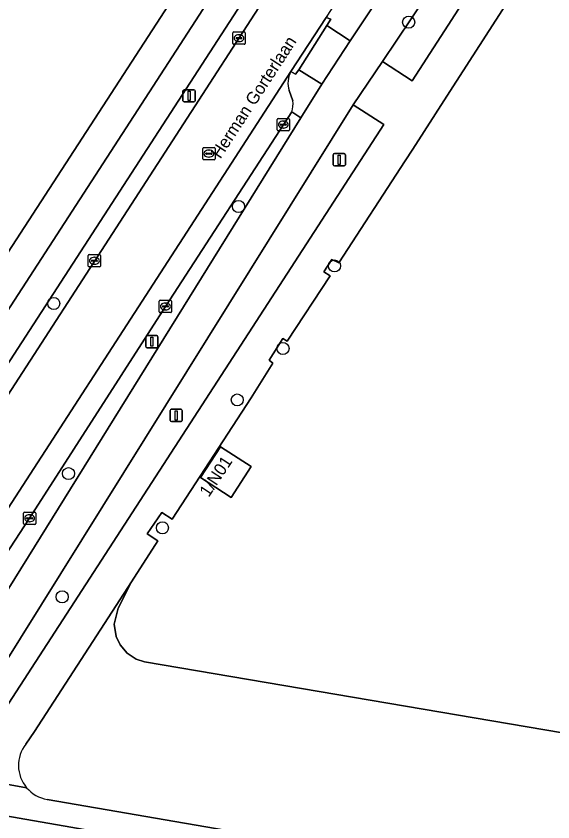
# Model space of a CAD drawing. Extents: x 161258 to 161838, y 380833 to 381727.
# Drawn here: x 161521.6 to 161565.2, y 380871.5 to 380937 of the extents above; entities that cross this region are included whole.
import ezdxf

# ---------------------------------------------------------------- set-up
doc = ezdxf.new("R2010")
doc.units = 0
for name, color, linetype in [('IMGEO_Berm_groen', 7, 'Continuous'), ('IMGEO_Berm_halfverhard', 7, 'Continuous'), ('IMGEO_Berm_open', 7, 'Continuous'), ('IMGEO_Boom', 7, 'Continuous'), ('IMGEO_Erf', 7, 'Continuous'), ('IMGEO_Fietspad_gesloten', 7, 'Continuous'), ('IMGEO_Kolk', 7, 'Continuous'), ('IMGEO_Lichtmast', 7, 'Continuous'), ('IMGEO_Loofbos', 7, 'Continuous'), ('IMGEO_Openbare_ruimte_label', 7, 'Continuous'), ('IMGEO_Pand', 7, 'Continuous'), ('IMGEO_Pand_nummerreeks', 7, 'Continuous'), ('IMGEO_Parkeervlak_open', 7, 'Continuous'), ('IMGEO_Rijbaan_lokaal_open', 7, 'Continuous'), ('IMGEO_Rioolput', 7, 'Continuous'), ('IMGEO_Voetpad_gesloten', 7, 'Continuous'), ('IMGEO_Voetpad_open', 7, 'Continuous')]:
    doc.layers.add(name, color=color, linetype=linetype)

msp = doc.modelspace()

# ---------------------------------------------------------------- linework, layer by layer
at = {"layer": 'IMGEO_Berm_groen'}
msp.add_lwpolyline([(161575.815, 380965.914), (161576.339, 380966.695), (161577.485, 380968.471), (161575.243, 380968.987), (161573.978, 380967.07), (161573.428, 380966.238), (161551.302, 380933.307), (161553.723, 380931.738)], close=True, dxfattribs=at)
for points in [[(161546.812, 380936.989), (161546.739, 380936.876), (161547.104, 380936.735), (161546.794, 380936.22), (161548.686, 380934.993), (161550.756, 380938.063)], [(161546.385, 380931.453), (161544.513, 380932.638), (161544.243, 380932.26), (161543.871, 380932.477)], [(161543.742, 380930.939), (161544.035, 380930.109)], [(161543.938, 380929.207), (161544.685, 380928.722), (161546.385, 380931.453)], [(161551.434, 380928.192), (161548.922, 380929.776), (161516.774, 380878.276), (161515.901, 380876.852)], [(161515.875, 380875.503), (161517.075, 380875.292), (161519.332, 380878.728), (161551.434, 380928.192)]]:
    msp.add_lwpolyline(points, dxfattribs=at)
for centre, radius, start, end in [((161545.488, 380931.567), 1.856, 150.63017, 199.78089), ((161542.148, 380929.856), 1.904, 340.07765, 7.64649)]:
    msp.add_arc(centre, radius, start, end, dxfattribs=at)
at = {"layer": 'IMGEO_Berm_halfverhard'}
msp.add_lwpolyline([(161544.685, 380928.722), (161543.938, 380929.207), (161533.683, 380913.408), (161522.653, 380896.207), (161515.229, 380884.867), (161513.994, 380883.019), (161515.665, 380882.025), (161515.927, 380882.459)], close=True, dxfattribs=at)
at = {"layer": 'IMGEO_Berm_open'}
msp.add_lwpolyline([(161544.901, 380943.304), (161544.547, 380943.54), (161551.119, 380953.696), (161550.334, 380954.192), (161506.413, 380886.439), (161503.381, 380881.765), (161504.523, 380881.003), (161505.64, 380882.718)], close=True, dxfattribs=at)
at = {"layer": 'IMGEO_Boom'}
for centre in [(161553.439, 380936.496), (161539.621, 380921.529), (161547.413, 380916.696), (161524.614, 380913.646), (161543.23, 380909.996), (161539.52, 380905.815), (161525.812, 380899.834), (161533.438, 380895.426), (161525.296, 380889.829)]:
    msp.add_circle(centre, 0.489, dxfattribs=at)
at = {"layer": 'IMGEO_Erf'}
for points in [[(161490.257, 380892.689), (161494.395, 380889.926), (161494.323, 380889.817), (161500.227, 380885.918), (161501.31, 380887.571), (161502.49, 380889.425), (161513.725, 380906.807), (161512.888, 380907.32), (161515.02, 380910.631), (161515.878, 380910.106), (161540.302, 380947.69), (161546.174, 380956.722), (161554.834, 380970.332), (161556.123, 380972.241), (161556.737, 380973.185), (161558.236, 380975.49), (161576.218, 381003.146)], [(161579.588, 380966.248), (161556.537, 380930.473), (161553.779, 380926.192), (161553.165, 380925.238), (161547.753, 380916.964), (161547.209, 380917.209), (161546.55, 380916.226), (161547.061, 380915.899), (161543.578, 380910.592), (161543.218, 380910.801), (161542.1, 380909.047), (161542.416, 380908.796), (161540.643, 380905.976), (161534.24, 380896.125), (161533.387, 380896.677), (161532.197, 380894.942), (161533.069, 380894.385), (161530.918, 380891.057), (161529.831, 380888.91), (161529.531, 380887.614), (161529.683, 380886.616), (161530.003, 380885.931), (161530.573, 380885.257), (161531.3, 380884.776), (161531.988, 380884.543), (161635.09, 380867.033)]]:
    msp.add_lwpolyline(points, dxfattribs=at)
msp.add_lwpolyline([(161539.026, 380897.897), (161536.533, 380899.52), (161538.15, 380902.004), (161540.639, 380900.399)], close=True, dxfattribs=at)
at = {"layer": 'IMGEO_Fietspad_gesloten'}
for points in [[(161595.079, 381027.823), (161594.29, 381026.415), (161590.696, 381020.856), (161581.633, 381006.84), (161581.562, 381006.731), (161578.938, 381002.688), (161504.207, 380887.394), (161498.991, 380879.345)], [(161608.896, 381024.645), (161604.863, 381018.421), (161604.793, 381018.314), (161595.419, 381004.467), (161595.345, 381004.358), (161592.619, 381000.32), (161590.6, 380997.205), (161582.149, 380984.599), (161579.947, 380981.315), (161576.319, 380975.904), (161571.939, 380969.459), (161570.664, 380967.582), (161565.851, 380960.445), (161550.756, 380938.063), (161548.686, 380934.993), (161546.385, 380931.453), (161544.685, 380928.722), (161515.927, 380882.459), (161515.665, 380882.025), (161513.423, 380878.315), (161512.107, 380876.132), (161511.097, 380874.45)], [(161515.901, 380876.852), (161516.774, 380878.276), (161548.922, 380929.776), (161551.302, 380933.307), (161573.428, 380966.238), (161573.978, 380967.07), (161575.243, 380968.987), (161579.692, 380975.331)], [(161493.75, 380876.843), (161499.475, 380875.817), (161500.162, 380876.872), (161500.997, 380878.155), (161503.381, 380881.765), (161506.413, 380886.439), (161550.334, 380954.192)], [(161591.978, 380859.82), (161583.327, 380861.142), (161518.201, 380872.481), (161510.384, 380873.954)]]:
    msp.add_lwpolyline(points, dxfattribs=at)
at = {"layer": 'IMGEO_Kolk'}
for p, q in [((161539.157, 380934.772), (161539.157, 380935.624)), ((161539.232, 380935.698), (161540.084, 380935.698)), ((161539.645, 380935.478), (161539.67, 380935.478)), ((161540.158, 380935.624), (161540.158, 380934.772)), ((161539.416, 380935.192), (161539.416, 380935.204)), ((161539.854, 380935.155), (161539.456, 380935.155)), ((161539.459, 380935.241), (161539.857, 380935.241)), ((161539.668, 380934.918), (161539.643, 380934.918)), ((161539.9, 380935.204), (161539.9, 380935.192)), ((161540.084, 380934.698), (161539.232, 380934.698)), ((161542.757, 380927.749), (161542.757, 380928.601)), ((161542.832, 380928.675), (161543.684, 380928.675)), ((161543.059, 380928.218), (161543.457, 380928.218)), ((161543.245, 380928.455), (161543.27, 380928.455)), ((161543.758, 380928.601), (161543.758, 380927.749)), ((161543.684, 380927.675), (161542.832, 380927.675)), ((161543.016, 380928.169), (161543.016, 380928.181)), ((161543.454, 380928.132), (161543.056, 380928.132)), ((161543.268, 380927.895), (161543.243, 380927.895)), ((161543.5, 380928.181), (161543.5, 380928.169)), ((161527.413, 380916.693), (161527.413, 380917.545)), ((161527.488, 380917.619), (161528.34, 380917.619)), ((161527.672, 380917.113), (161527.672, 380917.125)), ((161528.11, 380917.076), (161527.712, 380917.076)), ((161527.715, 380917.162), (161528.113, 380917.162)), ((161527.901, 380917.399), (161527.926, 380917.399)), ((161528.156, 380917.125), (161528.156, 380917.113)), ((161528.414, 380917.545), (161528.414, 380916.693)), ((161528.34, 380916.619), (161527.488, 380916.619)), ((161527.924, 380916.839), (161527.899, 380916.839)), ((161533.182, 380912.982), (161533.182, 380913.834)), ((161533.257, 380913.908), (161534.109, 380913.908)), ((161534.183, 380913.834), (161534.183, 380912.982)), ((161533.441, 380913.402), (161533.441, 380913.414)), ((161533.879, 380913.365), (161533.481, 380913.365)), ((161533.484, 380913.451), (161533.882, 380913.451)), ((161533.67, 380913.688), (161533.695, 380913.688)), ((161533.925, 380913.414), (161533.925, 380913.402)), ((161534.109, 380912.908), (161533.257, 380912.908)), ((161533.693, 380913.128), (161533.668, 380913.128)), ((161522.152, 380895.781), (161522.152, 380896.633)), ((161522.227, 380896.707), (161523.079, 380896.707)), ((161522.411, 380896.201), (161522.411, 380896.213)), ((161522.849, 380896.164), (161522.451, 380896.164)), ((161522.454, 380896.25), (161522.852, 380896.25)), ((161522.64, 380896.487), (161522.665, 380896.487)), ((161522.895, 380896.213), (161522.895, 380896.201)), ((161523.153, 380896.633), (161523.153, 380895.781)), ((161523.079, 380895.707), (161522.227, 380895.707)), ((161522.663, 380895.927), (161522.638, 380895.927))]:
    msp.add_line(p, q, dxfattribs=at)
for points in [[(161539.157, 380934.772), (161539.157, 380935.624)], [(161539.232, 380935.698), (161540.084, 380935.698)], [(161540.158, 380935.624), (161540.158, 380934.772)], [(161540.084, 380934.698), (161539.232, 380934.698)], [(161542.757, 380927.749), (161542.757, 380928.601)], [(161542.832, 380928.675), (161543.684, 380928.675)], [(161543.758, 380928.601), (161543.758, 380927.749)], [(161543.684, 380927.675), (161542.832, 380927.675)], [(161527.413, 380916.693), (161527.413, 380917.545)], [(161527.488, 380917.619), (161528.34, 380917.619)], [(161528.414, 380917.545), (161528.414, 380916.693)], [(161528.34, 380916.619), (161527.488, 380916.619)], [(161533.182, 380912.982), (161533.182, 380913.834)], [(161533.257, 380913.908), (161534.109, 380913.908)], [(161534.183, 380913.834), (161534.183, 380912.982)], [(161534.109, 380912.908), (161533.257, 380912.908)], [(161522.152, 380895.781), (161522.152, 380896.633)], [(161522.227, 380896.707), (161523.079, 380896.707)], [(161523.153, 380896.633), (161523.153, 380895.781)], [(161523.079, 380895.707), (161522.227, 380895.707)]]:
    msp.add_lwpolyline(points, dxfattribs=at)
for centre, radius, start, end in [((161539.234, 380935.622), 0.0765, 91.55205, 178.44795), ((161539.234, 380935.622), 0.0765, 91.55205, 178.44795), ((161540.082, 380935.622), 0.0765, 1.55205, 88.44795), ((161540.082, 380935.622), 0.0765, 1.55205, 88.44795), ((161539.234, 380934.774), 0.0765, 181.55205, 268.44795), ((161539.234, 380934.774), 0.0765, 181.55205, 268.44795), ((161539.456, 380935.201), 0.0403, 85.87752, 175.75265), ((161539.453, 380935.191), 0.0366, 178.93798, 274.71019), ((161539.857, 380935.198), 0.043, 264.86636, 352.45326), ((161539.861, 380935.203), 0.0386, 1.73085, 96.63898), ((161540.082, 380934.774), 0.0765, 271.55205, 358.44795), ((161540.082, 380934.774), 0.0765, 271.55205, 358.44795), ((161542.834, 380928.599), 0.0765, 91.55205, 178.44795), ((161542.834, 380928.599), 0.0765, 91.55205, 178.44795), ((161543.056, 380928.178), 0.0403, 85.87752, 175.75265), ((161543.461, 380928.18), 0.0386, 1.73085, 96.63898), ((161543.682, 380928.599), 0.0765, 1.55205, 88.44795), ((161543.682, 380928.599), 0.0765, 1.55205, 88.44795), ((161542.834, 380927.751), 0.0765, 181.55205, 268.44795), ((161542.834, 380927.751), 0.0765, 181.55205, 268.44795), ((161543.053, 380928.168), 0.0366, 178.93798, 274.71019), ((161543.457, 380928.175), 0.043, 264.86636, 352.45326), ((161543.682, 380927.751), 0.0765, 271.55205, 358.44795), ((161543.682, 380927.751), 0.0765, 271.55205, 358.44795), ((161527.49, 380917.543), 0.0765, 91.55205, 178.44795), ((161527.49, 380917.543), 0.0765, 91.55205, 178.44795), ((161527.712, 380917.122), 0.0403, 85.87752, 175.75265), ((161527.709, 380917.112), 0.0366, 178.93798, 274.71019), ((161528.113, 380917.119), 0.043, 264.86636, 352.45326), ((161528.117, 380917.124), 0.0386, 1.73085, 96.63898), ((161528.338, 380917.543), 0.0765, 1.55205, 88.44795), ((161528.338, 380917.543), 0.0765, 1.55205, 88.44795), ((161527.49, 380916.695), 0.0765, 181.55205, 268.44795), ((161527.49, 380916.695), 0.0765, 181.55205, 268.44795), ((161528.338, 380916.695), 0.0765, 271.55205, 358.44795), ((161528.338, 380916.695), 0.0765, 271.55205, 358.44795), ((161533.259, 380913.832), 0.0765, 91.55205, 178.44795), ((161533.259, 380913.832), 0.0765, 91.55205, 178.44795), ((161534.107, 380913.832), 0.0765, 1.55205, 88.44795), ((161534.107, 380913.832), 0.0765, 1.55205, 88.44795), ((161533.481, 380913.411), 0.0403, 85.87752, 175.75265), ((161533.478, 380913.401), 0.0366, 178.93798, 274.71019), ((161533.882, 380913.408), 0.043, 264.86636, 352.45326), ((161533.886, 380913.413), 0.0386, 1.73085, 96.63898), ((161533.259, 380912.984), 0.0765, 181.55205, 268.44795), ((161533.259, 380912.984), 0.0765, 181.55205, 268.44795), ((161534.107, 380912.984), 0.0765, 271.55205, 358.44795), ((161534.107, 380912.984), 0.0765, 271.55205, 358.44795), ((161522.229, 380896.631), 0.0765, 91.55205, 178.44795), ((161522.229, 380896.631), 0.0765, 91.55205, 178.44795), ((161522.451, 380896.21), 0.0403, 85.87752, 175.75265), ((161522.448, 380896.2), 0.0366, 178.93798, 274.71019), ((161522.852, 380896.207), 0.043, 264.86636, 352.45326), ((161522.856, 380896.212), 0.0386, 1.73085, 96.63898), ((161523.077, 380896.631), 0.0765, 1.55205, 88.44795), ((161523.077, 380896.631), 0.0765, 1.55205, 88.44795), ((161522.229, 380895.783), 0.0765, 181.55205, 268.44795), ((161522.229, 380895.783), 0.0765, 181.55205, 268.44795), ((161523.077, 380895.783), 0.0765, 271.55205, 358.44795), ((161523.077, 380895.783), 0.0765, 271.55205, 358.44795)]:
    msp.add_arc(centre, radius, start, end, dxfattribs=at)
for centre, major_axis, ratio, start_param, end_param in [((161539.644, 380935.198), (-0.387, 0.002), 0.722429, 4.712389, 7.853982), ((161539.669, 380935.198), (-0.39, 0.002), 0.717154, 1.570796, 4.712389), ((161543.244, 380928.175), (-0.387, 0.002), 0.722429, 4.712389, 7.853982), ((161543.269, 380928.175), (-0.39, 0.002), 0.717154, 1.570796, 4.712389), ((161527.9, 380917.119), (-0.387, 0.002), 0.722429, 4.712389, 7.853982), ((161527.925, 380917.119), (-0.39, 0.002), 0.717154, 1.570796, 4.712389), ((161533.669, 380913.408), (-0.387, 0.002), 0.722429, 4.712389, 7.853982), ((161533.694, 380913.408), (-0.39, 0.002), 0.717154, 1.570796, 4.712389), ((161522.639, 380896.207), (-0.387, 0.002), 0.722429, 4.712389, 7.853982), ((161522.664, 380896.207), (-0.39, 0.002), 0.717154, 1.570796, 4.712389)]:
    msp.add_ellipse(centre, major_axis=major_axis, ratio=ratio, start_param=start_param, end_param=end_param, dxfattribs=at)
at = {"layer": 'IMGEO_Lichtmast'}
for p, q in [((161535.109, 380930.113), (161535.109, 380930.913)), ((161535.109, 380930.913), (161535.109, 380930.113)), ((161535.209, 380931.013), (161535.999, 380931.013)), ((161535.999, 380931.013), (161535.209, 380931.013)), ((161536.099, 380930.913), (161536.099, 380930.113)), ((161536.099, 380930.113), (161536.099, 380930.913)), ((161535.999, 380930.013), (161535.209, 380930.013)), ((161535.209, 380930.013), (161535.999, 380930.013)), ((161547.305, 380924.923), (161547.305, 380925.723)), ((161547.305, 380925.723), (161547.305, 380924.923)), ((161547.405, 380925.823), (161548.195, 380925.823)), ((161548.195, 380925.823), (161547.405, 380925.823)), ((161548.295, 380925.723), (161548.295, 380924.923)), ((161548.295, 380924.923), (161548.295, 380925.723)), ((161548.195, 380924.823), (161547.405, 380924.823)), ((161547.405, 380924.823), (161548.195, 380924.823)), ((161532.088, 380910.151), (161532.088, 380910.951)), ((161532.088, 380910.951), (161532.088, 380910.151)), ((161532.188, 380911.051), (161532.978, 380911.051)), ((161532.978, 380911.051), (161532.188, 380911.051)), ((161533.078, 380910.951), (161533.078, 380910.151)), ((161533.078, 380910.151), (161533.078, 380910.951)), ((161532.978, 380910.051), (161532.188, 380910.051)), ((161532.188, 380910.051), (161532.978, 380910.051)), ((161534.064, 380904.155), (161534.064, 380904.955)), ((161534.064, 380904.955), (161534.064, 380904.155)), ((161534.164, 380905.055), (161534.954, 380905.055)), ((161534.954, 380905.055), (161534.164, 380905.055)), ((161535.054, 380904.955), (161535.054, 380904.155)), ((161535.054, 380904.155), (161535.054, 380904.955)), ((161534.954, 380904.055), (161534.164, 380904.055)), ((161534.164, 380904.055), (161534.954, 380904.055))]:
    msp.add_line(p, q, dxfattribs=at)
for points in [[(161535.529, 380930.888), (161535.679, 380930.888), (161535.679, 380930.138), (161535.529, 380930.138), (161535.529, 380930.888)], [(161547.725, 380925.698), (161547.875, 380925.698), (161547.875, 380924.948), (161547.725, 380924.948), (161547.725, 380925.698)], [(161532.508, 380910.926), (161532.658, 380910.926), (161532.658, 380910.176), (161532.508, 380910.176), (161532.508, 380910.926)], [(161534.484, 380904.93), (161534.634, 380904.93), (161534.634, 380904.18), (161534.484, 380904.18), (161534.484, 380904.93)]]:
    msp.add_lwpolyline(points, dxfattribs=at)
for centre, start, end in [((161535.209, 380930.913), 90, 180), ((161535.209, 380930.913), 90, 180), ((161535.999, 380930.913), 0, 90), ((161535.999, 380930.913), 360, 90), ((161535.209, 380930.113), 180, 270), ((161535.209, 380930.113), 180, 270), ((161535.999, 380930.113), 270, 0), ((161535.999, 380930.113), 270, 0), ((161547.405, 380925.723), 90, 180), ((161547.405, 380925.723), 90, 180), ((161548.195, 380925.723), 0, 90), ((161548.195, 380925.723), 360, 90), ((161547.405, 380924.923), 180, 270), ((161547.405, 380924.923), 180, 270), ((161548.195, 380924.923), 270, 0), ((161548.195, 380924.923), 270, 0), ((161532.188, 380910.951), 90, 180), ((161532.188, 380910.951), 90, 180), ((161532.978, 380910.951), 0, 90), ((161532.978, 380910.951), 360, 90), ((161532.188, 380910.151), 180, 270), ((161532.188, 380910.151), 180, 270), ((161532.978, 380910.151), 270, 0), ((161532.978, 380910.151), 270, 0), ((161534.164, 380904.955), 90, 180), ((161534.164, 380904.955), 90, 180), ((161534.954, 380904.955), 0, 90), ((161534.954, 380904.955), 360, 90), ((161534.164, 380904.155), 180, 270), ((161534.164, 380904.155), 180, 270), ((161534.954, 380904.155), 270, 0), ((161534.954, 380904.155), 270, 0)]:
    msp.add_arc(centre, 0.1, start, end, dxfattribs=at)
at = {"layer": 'IMGEO_Loofbos'}
for points in [[(161531.988, 380884.543), (161531.3, 380884.776), (161530.573, 380885.257), (161530.003, 380885.931), (161529.683, 380886.616), (161529.531, 380887.614), (161529.831, 380888.91), (161530.918, 380891.057), (161523.047, 380878.902), (161522.349, 380877.864)], [(161630.977, 380863.784), (161630.549, 380865.324), (161635.09, 380867.033), (161531.988, 380884.543)], [(161524.083, 380873.377), (161584.252, 380862.998), (161592.126, 380861.78)]]:
    msp.add_lwpolyline(points, dxfattribs=at)
for centre, radius, start, end in [((161524.538, 380876.131), 2.792, 141.63598, 220.24346), ((161524.535, 380876.125), 2.785, 220.18835, 260.66855)]:
    msp.add_arc(centre, radius, start, end, dxfattribs=at)
at = {"layer": 'IMGEO_Pand'}
msp.add_lwpolyline([(161539.026, 380897.897), (161540.639, 380900.399), (161538.15, 380902.004), (161536.533, 380899.52)], close=True, dxfattribs=at)
at = {"layer": 'IMGEO_Parkeervlak_open'}
for points in [[(161543.871, 380932.477), (161510.889, 380881.596)], [(161544.035, 380930.109), (161543.742, 380930.939)], [(161513.994, 380883.019), (161515.229, 380884.867), (161522.653, 380896.207), (161533.683, 380913.408), (161543.938, 380929.207)]]:
    msp.add_lwpolyline(points, dxfattribs=at)
for centre, radius, start, end in [((161545.488, 380931.567), 1.856, 150.63017, 199.78089), ((161542.148, 380929.856), 1.904, 340.07765, 7.64649)]:
    msp.add_arc(centre, radius, start, end, dxfattribs=at)
at = {"layer": 'IMGEO_Rijbaan_lokaal_open'}
msp.add_lwpolyline([(161510.462, 380880.94), (161510.889, 380881.596), (161543.871, 380932.477), (161546.739, 380936.876), (161546.812, 380936.989), (161564.612, 380964.444), (161560.391, 380967.118), (161551.487, 380953.442), (161544.901, 380943.304), (161505.64, 380882.718), (161504.523, 380881.003), (161502.618, 380878.101), (161500.831, 380875.559), (161509.795, 380873.992)], dxfattribs=at)
at = {"layer": 'IMGEO_Rioolput'}
for p, q in [((161536.712, 380925.393), (161536.712, 380926.245)), ((161536.787, 380926.319), (161537.639, 380926.319)), ((161537.713, 380926.245), (161537.713, 380925.393)), ((161536.971, 380925.813), (161536.971, 380925.825)), ((161537.409, 380925.776), (161537.011, 380925.776)), ((161537.014, 380925.862), (161537.412, 380925.862)), ((161537.2, 380926.099), (161537.225, 380926.099)), ((161537.455, 380925.825), (161537.455, 380925.813)), ((161537.639, 380925.319), (161536.787, 380925.319)), ((161537.223, 380925.539), (161537.198, 380925.539))]:
    msp.add_line(p, q, dxfattribs=at)
for points in [[(161536.712, 380925.393), (161536.712, 380926.245)], [(161536.787, 380926.319), (161537.639, 380926.319)], [(161537.713, 380926.245), (161537.713, 380925.393)], [(161537.639, 380925.319), (161536.787, 380925.319)]]:
    msp.add_lwpolyline(points, dxfattribs=at)
for centre, radius, start, end in [((161536.789, 380926.243), 0.0765, 91.55205, 178.44795), ((161536.789, 380926.243), 0.0765, 91.55205, 178.44795), ((161537.637, 380926.243), 0.0765, 1.55205, 88.44795), ((161537.637, 380926.243), 0.0765, 1.55205, 88.44795), ((161537.011, 380925.822), 0.0403, 85.87752, 175.75265), ((161537.008, 380925.812), 0.0366, 178.93798, 274.71019), ((161537.412, 380925.819), 0.043, 264.86636, 352.45326), ((161537.416, 380925.824), 0.0386, 1.73085, 96.63898), ((161536.789, 380925.395), 0.0765, 181.55205, 268.44795), ((161536.789, 380925.395), 0.0765, 181.55205, 268.44795), ((161537.637, 380925.395), 0.0765, 271.55205, 358.44795), ((161537.637, 380925.395), 0.0765, 271.55205, 358.44795)]:
    msp.add_arc(centre, radius, start, end, dxfattribs=at)
for centre, major_axis, ratio, start_param, end_param in [((161537.199, 380925.819), (-0.387, 0.002), 0.722429, 4.712389, 7.853982), ((161537.224, 380925.819), (-0.39, 0.002), 0.717154, 1.570796, 4.712389)]:
    msp.add_ellipse(centre, major_axis=major_axis, ratio=ratio, start_param=start_param, end_param=end_param, dxfattribs=at)
at = {"layer": 'IMGEO_Voetpad_gesloten'}
msp.add_lwpolyline([(161546.794, 380936.22), (161547.104, 380936.735), (161546.739, 380936.876), (161543.871, 380932.477), (161544.243, 380932.26), (161544.513, 380932.638)], close=True, dxfattribs=at)
at = {"layer": 'IMGEO_Voetpad_open'}
for points in [[(161578.938, 381002.688), (161581.562, 381006.731), (161581.633, 381006.84), (161578.923, 381007.348), (161578.828, 381007.201), (161576.218, 381003.146), (161558.236, 380975.49), (161556.737, 380973.185), (161556.123, 380972.241), (161554.834, 380970.332), (161546.174, 380956.722), (161540.302, 380947.69), (161515.878, 380910.106), (161513.725, 380906.807), (161502.49, 380889.425), (161501.31, 380887.571), (161500.227, 380885.918), (161499.245, 380884.419), (161496.974, 380880.952)], [(161498.991, 380879.345), (161504.207, 380887.394), (161578.938, 381002.688)], [(161522.349, 380877.864), (161523.047, 380878.902), (161530.918, 380891.057), (161533.069, 380894.385), (161532.197, 380894.942), (161533.387, 380896.677), (161534.24, 380896.125), (161540.643, 380905.976), (161542.416, 380908.796), (161542.1, 380909.047), (161543.218, 380910.801), (161543.578, 380910.592), (161547.061, 380915.899), (161546.55, 380916.226), (161547.209, 380917.209), (161547.753, 380916.964), (161553.165, 380925.238), (161553.779, 380926.192), (161556.537, 380930.473), (161579.588, 380966.248)], [(161575.815, 380965.914), (161553.723, 380931.738), (161551.302, 380933.307), (161548.922, 380929.776), (161551.434, 380928.192), (161519.332, 380878.728), (161517.075, 380875.292), (161522.407, 380874.328)], [(161522.407, 380874.328), (161517.075, 380875.292), (161515.875, 380875.503)], [(161592.126, 380861.78), (161584.252, 380862.998), (161524.083, 380873.377)], [(161518.201, 380872.481), (161583.327, 380861.142), (161591.978, 380859.82)]]:
    msp.add_lwpolyline(points, dxfattribs=at)
msp.add_lwpolyline([(161544.513, 380932.638), (161546.385, 380931.453), (161548.686, 380934.993), (161546.794, 380936.22)], close=True, dxfattribs=at)
for centre, radius, start, end in [((161524.538, 380876.131), 2.792, 141.63598, 220.24346), ((161524.535, 380876.125), 2.785, 220.18835, 260.66855)]:
    msp.add_arc(centre, radius, start, end, dxfattribs=at)

# ---------------------------------------------------------------- texts
at = {"layer": 'IMGEO_Openbare_ruimte_label'}
msp.add_text('Herman Gorterlaan', height=1, rotation=56.99294, dxfattribs=at).set_placement((161538.145, 380925.341))
at = {"layer": 'IMGEO_Pand_nummerreeks'}
msp.add_text('1/N01', height=1, rotation=56.46395, dxfattribs=at).set_placement((161537.198, 380897.859))

doc.saveas('drawing.dxf')
